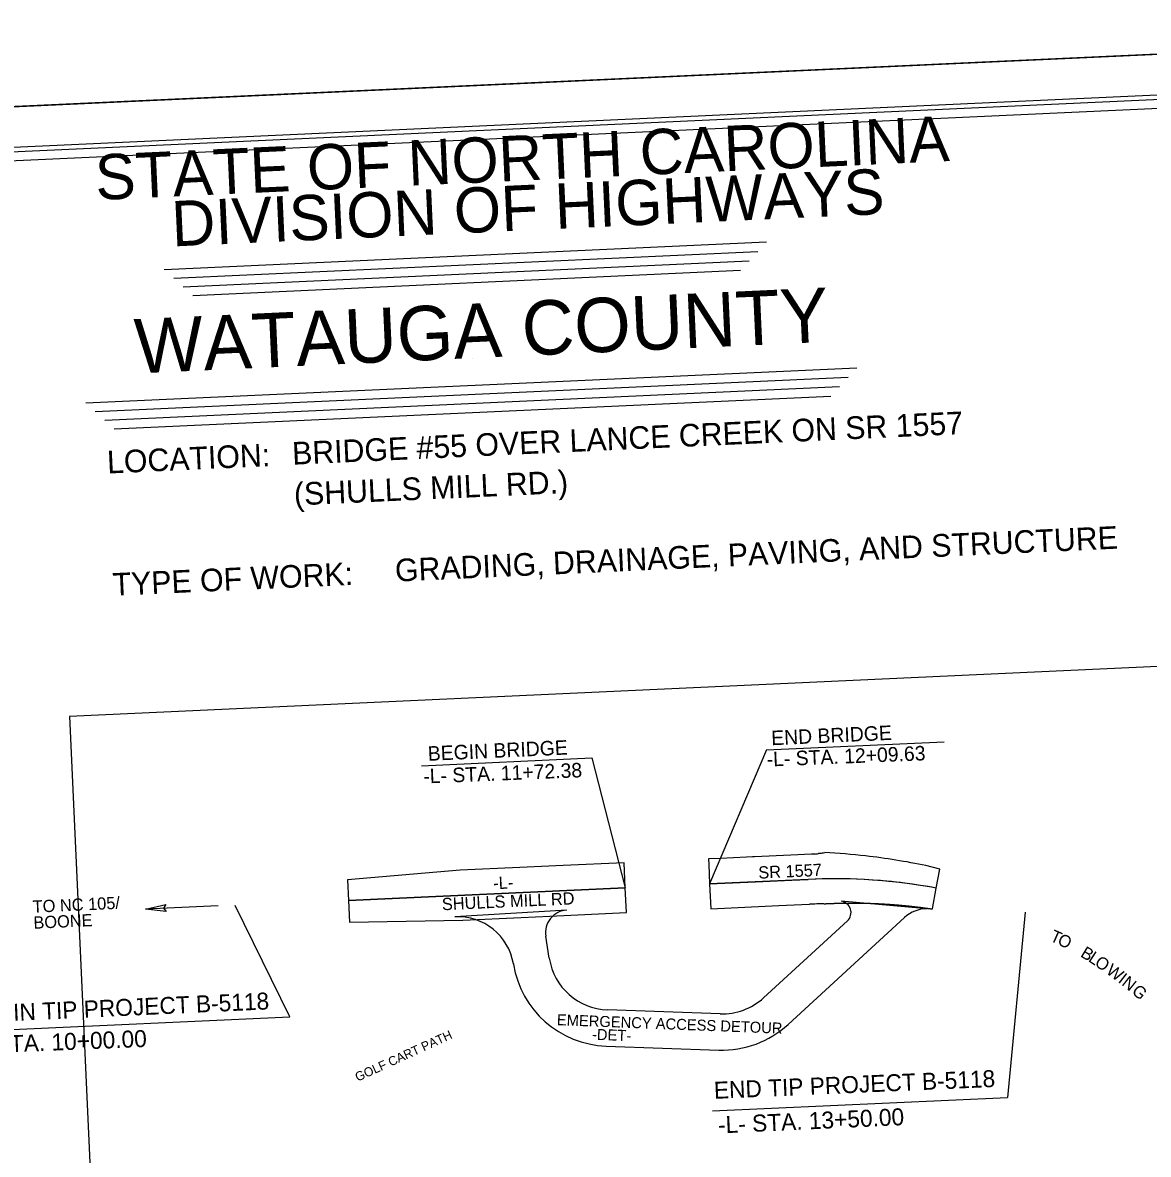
# Model space of a CAD drawing. Extents: x 1190067 to 1192950, y 891516 to 893460.
# Drawn here: x 1191189.1 to 1191686.2, y 892960.2 to 893459.6 of the extents above; entities that cross this region are included whole.
import ezdxf

# ---------------------------------------------------------------- set-up
doc = ezdxf.new("R2010")
doc.units = 0
for name, color, linetype in [('Prop DSN Text', 7, 'Continuous'), ('Prop Shade Light', 7, 'Continuous'), ('Prop Shade Medium', 7, 'Continuous'), ('Prop Terminator CELL', 7, 'Continuous'), ('Scratch_Level_3', 7, 'Continuous'), ('Sheet Cutting Line CELL', 7, 'Continuous'), ('Sheet Data Field CELL', 7, 'Continuous'), ('Sheet Plot Border Inside CELL', 7, 'Continuous'), ('Sheet Plot Border Outside CELL', 7, 'Continuous'), ('Sheet Title CELL', 7, 'Continuous'), ('Sheet Title Data Points CELL', 7, 'Continuous')]:
    doc.layers.add(name, color=color, linetype=linetype)

msp = doc.modelspace()

# ---------------------------------------------------------------- linework, layer by layer
at = {"layer": 'Prop DSN Text'}
for p, q in [((1191517.52, 893138.63), (1191596.05, 893142.22)), ((1191517.52, 893138.63), (1191492.4, 893079.53)), ((1191365.25, 893131.66), (1191440.36, 893135.1)), ((1191440.36, 893135.1), (1191455.19, 893077.83)), ((1191275.47, 893069.89), (1191243.33, 893068.42)), ((1191306.99, 893020.8), (1191282.99, 893069.95)), ((1191631.79, 893067.11), (1191623.92, 892985.28)), ((1191161.2, 893014.13), (1191306.99, 893020.8)), ((1191493.63, 892979.32), (1191623.92, 892985.28))]:
    msp.add_line(p, q, dxfattribs=at)
at = {"layer": 'Prop Shade Light'}
for p, q in [((1191588.5, 893068.56), (1191550.46, 893071.85)), ((1191429.32, 893067.94), (1191379.88, 893065.01)), ((1191553.24, 893063.2), (1191516.27, 893029.27)), ((1191527.09, 893017.48), (1191578.45, 893064.62)), ((1191421.61, 893046.69), (1191420.08, 893056.4)), ((1191497.07, 893022.18), (1191447.33, 893023.92)), ((1191446.78, 893007.93), (1191496.51, 893006.19))]:
    msp.add_line(p, q, dxfattribs=at)
msp.add_lwpolyline([(1191405.81, 893044.2), (1191405.81, 893044.2)], dxfattribs=at)
for centre, radius, start, end in [((1191549.86, 893066.88), 5, 312.5411, 83.0925), ((1191429.95, 893057.96), 10, 93.6582, 188.9764), ((1191588.59, 893053.57), 15, 90.3526, 132.5411), ((1191381.15, 893040.04), 25, 9.5636, 92.9116), ((1191448.28, 893050.91), 27, 188.9764, 267.9944), ((1191448.28, 893050.91), 43, 188.9764, 189.1922), ((1191381.15, 893040.04), 25, 9.1923, 9.1924), ((1191448.28, 893050.91), 43, 189.1923, 267.9944), ((1191498.01, 893049.17), 27, 267.9944, 312.5411), ((1191498.01, 893049.17), 43, 267.9944, 312.5411)]:
    msp.add_arc(centre, radius, start, end, dxfattribs=at)
at = {"layer": 'Prop Shade Medium'}
for p, q in [((1191528.23, 893092.18), (1191512.25, 893091.45)), ((1191537.42, 893092.6), (1191528.23, 893092.18)), ((1191538.92, 893092.7), (1191537.42, 893092.6)), ((1191454.69, 893088.82), (1191427.79, 893087.58)), ((1191455.19, 893077.83), (1191454.69, 893088.82)), ((1191497.18, 893090.76), (1191491.9, 893090.52)), ((1191491.9, 893090.52), (1191492.01, 893088.14)), ((1191492.01, 893088.14), (1191492.4, 893079.53)), ((1191594.01, 893086.02), (1191587.94, 893087.59)), ((1191592.48, 893077.68), (1191594.01, 893086.02)), ((1191382.34, 893085.51), (1191332.53, 893081.3)), ((1191332.53, 893081.3), (1191332.94, 893072.23)), ((1191535.97, 893081.52), (1191492.4, 893079.53)), ((1191512.75, 893080.46), (1191528.74, 893081.19)), ((1191528.74, 893081.19), (1191535.97, 893081.52)), ((1191332.94, 893072.23), (1191455.19, 893077.83)), ((1191455.19, 893077.83), (1191332.94, 893072.23)), ((1191455.7, 893066.84), (1191455.19, 893077.83)), ((1191492.4, 893079.53), (1191512.75, 893080.46)), ((1191492.4, 893079.53), (1191492.91, 893068.54)), ((1191590.78, 893068.46), (1191592.48, 893077.68)), ((1191332.94, 893072.23), (1191333.38, 893062.68)), ((1191333.38, 893062.68), (1191383.44, 893063.53))]:
    msp.add_line(p, q, dxfattribs=at)
for points in [[(1191512.25, 893091.45), (1191511.33, 893091.41), (1191508.73, 893091.29), (1191497.18, 893090.76)], [(1191427.79, 893087.58), (1191427.79, 893087.58), (1191408.57, 893086.7), (1191382.34, 893085.51)], [(1191383.44, 893063.53), (1191409.14, 893064.71), (1191421.87, 893065.29), (1191455.7, 893066.84)], [(1191492.91, 893068.54), (1191522.92, 893069.91), (1191536.47, 893070.53)]]:
    msp.add_lwpolyline(points, dxfattribs=at)
for centre, radius, start, end in [((1191535.25, 893131.59), 39.06, 275.3979, 277.7646), ((1191535.25, 893131.59), 39.06, 278.914, 281.7955), ((1191527.61, 892795.99), 297.77, 83.5081, 86.9917), ((1191527.61, 892795.99), 297.77, 78.311, 83.5081), ((1191547.39, 892831.78), 250, 86.9447, 92.6195), ((1191547.39, 892831.78), 250, 79.6108, 92.6195), ((1191547.39, 892831.78), 250, 79.6108, 86.9447), ((1191547.39, 892831.78), 239, 91.07, 92.6195)]:
    msp.add_arc(centre, radius, start, end, dxfattribs=at)
for points, degree in [([(1191541.3, 893093), (1191541.05, 893092.96), (1191540.79, 893092.92), (1191540.53, 893092.89)], 2), ([(1191542.93, 893070.74), (1191543.15, 893070.75), (1191543.36, 893070.76), (1191543.58, 893070.77), (1191543.79, 893070.79), (1191544.01, 893070.8), (1191544.22, 893070.81), (1191544.44, 893070.82), (1191544.65, 893070.83), (1191544.87, 893070.83), (1191545.08, 893070.84), (1191545.3, 893070.85), (1191545.51, 893070.86), (1191545.73, 893070.87), (1191545.94, 893070.88), (1191546.16, 893070.89), (1191546.37, 893070.9), (1191546.59, 893070.9), (1191546.81, 893070.91), (1191547.02, 893070.92), (1191547.24, 893070.93), (1191547.45, 893070.93), (1191547.67, 893070.94), (1191547.88, 893070.95), (1191548.1, 893070.95), (1191548.31, 893070.96), (1191548.53, 893070.97), (1191548.74, 893070.97), (1191548.96, 893070.98), (1191549.18, 893070.98), (1191549.39, 893070.99), (1191549.61, 893071), (1191549.82, 893071), (1191550.04, 893071.01), (1191550.25, 893071.01), (1191550.47, 893071.01), (1191550.68, 893071.02), (1191550.9, 893071.02), (1191551.12, 893071.03), (1191551.33, 893071.03), (1191551.55, 893071.03), (1191551.76, 893071.04), (1191551.98, 893071.04), (1191552.19, 893071.04), (1191552.41, 893071.05), (1191552.63, 893071.05), (1191552.84, 893071.05), (1191553.06, 893071.05), (1191553.27, 893071.06), (1191553.49, 893071.06), (1191553.7, 893071.06), (1191553.92, 893071.06), (1191554.14, 893071.06), (1191554.35, 893071.06), (1191554.57, 893071.06), (1191554.78, 893071.06), (1191555, 893071.06), (1191555.22, 893071.06), (1191555.43, 893071.06), (1191555.65, 893071.06), (1191555.86, 893071.06), (1191556.08, 893071.06), (1191556.29, 893071.06), (1191556.51, 893071.06), (1191556.73, 893071.06), (1191556.94, 893071.06), (1191557.16, 893071.06), (1191557.37, 893071.06), (1191557.59, 893071.05), (1191557.81, 893071.05), (1191558.02, 893071.05), (1191558.24, 893071.05), (1191558.45, 893071.04), (1191558.61, 893071.04), (1191558.76, 893071.04), (1191558.92, 893071.04)], 3), ([(1191558.92, 893071.04), (1191558.98, 893071.04), (1191559.04, 893071.04), (1191559.1, 893071.04), (1191559.32, 893071.03), (1191559.53, 893071.03), (1191559.75, 893071.02), (1191559.96, 893071.02), (1191560.18, 893071.02), (1191560.4, 893071.01), (1191560.61, 893071.01), (1191560.83, 893071), (1191561.04, 893071), (1191561.26, 893070.99), (1191561.48, 893070.99), (1191561.69, 893070.98), (1191561.91, 893070.97), (1191562.12, 893070.97), (1191562.34, 893070.96), (1191562.55, 893070.96), (1191562.77, 893070.95), (1191562.99, 893070.94), (1191563.2, 893070.94), (1191563.42, 893070.93), (1191563.63, 893070.92), (1191563.85, 893070.91), (1191564.07, 893070.91), (1191564.28, 893070.9), (1191564.5, 893070.89), (1191564.71, 893070.88), (1191564.93, 893070.87), (1191565.15, 893070.86), (1191565.36, 893070.86), (1191565.58, 893070.85), (1191565.79, 893070.84), (1191566.01, 893070.83), (1191566.23, 893070.82), (1191566.44, 893070.81), (1191566.66, 893070.8), (1191566.87, 893070.79), (1191567.09, 893070.78), (1191567.31, 893070.77), (1191567.52, 893070.75), (1191567.74, 893070.74), (1191567.95, 893070.73), (1191568.17, 893070.72), (1191568.38, 893070.71), (1191568.6, 893070.7), (1191568.82, 893070.69), (1191569.03, 893070.67), (1191569.25, 893070.66), (1191569.46, 893070.65), (1191569.68, 893070.64), (1191569.9, 893070.62), (1191570.11, 893070.61), (1191570.33, 893070.6), (1191570.54, 893070.58), (1191570.76, 893070.57), (1191570.97, 893070.55), (1191571.19, 893070.54), (1191571.41, 893070.53), (1191571.62, 893070.51), (1191571.84, 893070.5), (1191572.05, 893070.48), (1191572.27, 893070.47), (1191572.49, 893070.45), (1191572.7, 893070.44), (1191572.92, 893070.42), (1191573.13, 893070.4), (1191573.35, 893070.39), (1191573.56, 893070.37), (1191573.78, 893070.35), (1191574, 893070.34), (1191574.21, 893070.32), (1191574.43, 893070.3), (1191574.64, 893070.29), (1191574.73, 893070.28), (1191574.81, 893070.27), (1191574.89, 893070.27)], 3), ([(1191574.89, 893070.27), (1191575.03, 893070.26), (1191575.16, 893070.24), (1191575.29, 893070.23), (1191575.51, 893070.22), (1191575.72, 893070.2), (1191575.94, 893070.18), (1191576.15, 893070.16), (1191576.37, 893070.14), (1191576.58, 893070.12), (1191576.8, 893070.1), (1191577.01, 893070.08), (1191577.23, 893070.06), (1191577.45, 893070.04), (1191577.66, 893070.02), (1191577.88, 893070), (1191578.09, 893069.98), (1191578.31, 893069.96), (1191578.52, 893069.94), (1191578.74, 893069.92), (1191578.95, 893069.9), (1191579.17, 893069.88), (1191579.39, 893069.86), (1191579.6, 893069.83), (1191579.82, 893069.81), (1191580.03, 893069.79), (1191580.25, 893069.77), (1191580.46, 893069.74), (1191580.68, 893069.72), (1191580.89, 893069.7), (1191581.11, 893069.68), (1191581.32, 893069.65), (1191581.54, 893069.63), (1191581.75, 893069.61), (1191581.97, 893069.58), (1191582.18, 893069.56), (1191582.4, 893069.53), (1191582.61, 893069.51), (1191582.83, 893069.48), (1191583.05, 893069.46), (1191583.26, 893069.43), (1191583.48, 893069.41), (1191583.69, 893069.38), (1191583.91, 893069.36), (1191584.12, 893069.33), (1191584.34, 893069.3), (1191584.55, 893069.28), (1191584.77, 893069.25), (1191584.98, 893069.23), (1191585.2, 893069.2), (1191585.41, 893069.17), (1191585.63, 893069.14), (1191585.84, 893069.12), (1191586.06, 893069.09), (1191586.27, 893069.06), (1191586.49, 893069.03), (1191586.7, 893069.01), (1191586.92, 893068.98), (1191587.13, 893068.95), (1191587.35, 893068.92), (1191587.56, 893068.89), (1191587.78, 893068.86), (1191587.99, 893068.83), (1191588.2, 893068.8), (1191588.42, 893068.77), (1191588.63, 893068.74), (1191588.85, 893068.71), (1191589.06, 893068.68), (1191589.28, 893068.65), (1191589.49, 893068.62), (1191589.92, 893068.57), (1191590.35, 893068.51), (1191590.78, 893068.46)], 3)]:
    msp.add_open_spline(points, degree=degree, dxfattribs=at)
at = {"layer": 'Prop Terminator CELL'}
msp.add_lwpolyline([(1191252.39, 893067.28), (1191243.33, 893068.42), (1191252.3, 893070.43), (1191251.22, 893068.78)], close=True, dxfattribs=at)
at = {"layer": 'Scratch_Level_3'}
msp.add_lwpolyline([(1191229.35, 892723.98), (1191796.57, 892749.93), (1191776.92, 893179.4), (1191209.7, 893153.45)], close=True, dxfattribs=at)
at = {"layer": 'Sheet Cutting Line CELL'}
msp.add_line((1190649.32, 893398.03), (1191995.11, 893459.6), dxfattribs=at)
at = {"layer": 'Sheet Plot Border Inside CELL'}
msp.add_lwpolyline([(1190699.11, 892537.37), (1192030.91, 892598.3), (1191992.34, 893441.49), (1190660.53, 893380.56)], close=True, dxfattribs=at)
at = {"layer": 'Sheet Plot Border Outside CELL'}
msp.add_lwpolyline([(1191995.11, 893459.6), (1190649.32, 893398.03), (1190689.54, 892518.96), (1192035.33, 892580.53)], close=True, dxfattribs=at)
at = {"layer": 'Sheet Title CELL'}
for p, q in [((1191251.64, 893350.67), (1191517.56, 893362.84)), ((1191255.81, 893346.86), (1191513.74, 893358.66)), ((1191259.99, 893343.04), (1191509.93, 893354.49)), ((1191264.17, 893339.23), (1191506.12, 893350.31)), ((1191216.97, 893291.75), (1191557.42, 893307.32)), ((1191221.15, 893287.94), (1191553.6, 893303.14)), ((1191225.33, 893284.12), (1191549.79, 893298.97)), ((1191229.51, 893280.31), (1191545.98, 893294.78))]:
    msp.add_line(p, q, dxfattribs=at)
for points in [[(1191974.46, 893438.63), (1190791.68, 893384.53)], [(1191970.64, 893434.46), (1190835.83, 893382.54)]]:
    msp.add_lwpolyline(points, dxfattribs=at)
at = {"layer": 'Sheet Title Data Points CELL'}
for p, q in [((1191387.89, 893311.5), (1191387.89, 893311.5)), ((1191485.81, 893272.45), (1191485.81, 893272.45))]:
    msp.add_line(p, q, dxfattribs=at)

# ---------------------------------------------------------------- texts
at = {"layer": 'Prop DSN Text'}
for s, height, rotation, p in [('END BRIDGE', 6.4, 2.5982, (1191519.77, 893140.69)), ('BEGIN BRIDGE', 6.4, 2.5982, (1191368.13, 893133.81)), ('-L- STA. 12+09.63', 6.4, 2.2753, (1191517.73, 893131.29)), ('-L- STA. 11+72.38', 6.4, 2.2753, (1191366.12, 893123.81)), ('SR 1557', 5.4, 2.5982, (1191514.04, 893081.8)), ('-L-', 5.4, 2.5982, (1191397, 893077.13)), ('TO NC 105/', 5.4, 2.6195, (1191193.64, 893066.77)), ('SHULLS MILL RD', 5.4, 2.5982, (1191374.32, 893067.86)), ('BOONE', 5.4, 2.6195, (1191193.97, 893059.69)), ('T', 5.4, 335.914, (1191642.34, 893054.54)), ('O', 5.4, 334.0599, (1191645.62, 893053.07)), ('B', 5.4, 328.6297, (1191655.8, 893047.68)), ('L', 5.4, 327.0389, (1191659.28, 893045.55)), ('O', 5.4, 325.8877, (1191662.06, 893043.75)), ('W', 5.4, 324.1208, (1191667.11, 893040.28)), ('I', 5.4, 322.0067, (1191672.45, 893036.35)), ('N', 5.4, 321.3339, (1191674.04, 893035.12)), ('BEGIN TIP PROJECT B-5118', 7.5, 2.5982, (1191163.89, 893018.07)), ('G', 5.4, 319.4263, (1191678.46, 893031.54)), ('EMERGENCY ACCESS DETOUR', 4.86, 357.8265, (1191424.9, 893017.17)), ('-L- STA. 10+00.00', 7.5, 2.2753, (1191161.86, 893004.32)), ('GOLF CART PATH', 4, 24.5617, (1191337.01, 892992.2)), ('-DET-', 4.86, 357.8265, (1191440.39, 893010.75)), ('END TIP PROJECT B-5118', 7.5, 2.4356, (1191494.47, 892984.64)), ('-L- STA. 13+50.00', 7.5, 2.5888, (1191496.31, 892969.37))]:
    msp.add_text(s, height=height, rotation=rotation, dxfattribs=at).set_placement(p)
at = {"layer": 'Sheet Data Field CELL'}
for s, height, p in [('WATAUGA COUNTY', 24, (1191239.02, 893304.76)), ('BRIDGE #55 OVER LANCE CREEK ON SR 1557  ', 10.0001, (1191308.29, 893264.49)), ('(SHULLS MILL RD.)                       ', 10.0001, (1191309.11, 893246.51)), ('GRADING, DRAINAGE, PAVING, AND STRUCTURE', 10.0001, (1191353.72, 893212.88))]:
    msp.add_text(s, height=height, rotation=2.6195, dxfattribs=at).set_placement(p)
at = {"layer": 'Sheet Title CELL'}
for s, height, p in [('STATE OF NORTH CAROLINA', 19.9999, (1191221.56, 893381.29)), ('DIVISION OF HIGHWAYS', 19.9999, (1191255.26, 893360.81)), ('LOCATION: ', 10, (1191226.57, 893260.6)), ('TYPE OF WORK:', 10.0001, (1191229.03, 893206.64))]:
    msp.add_text(s, height=height, rotation=2.6195, dxfattribs=at).set_placement(p)

doc.saveas('drawing.dxf')
